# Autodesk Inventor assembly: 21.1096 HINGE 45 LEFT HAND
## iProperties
Created: 2007-01
Part Number: 21.1096 HINGE 45 LEFT HAND
Document SubType Name: Assembly
Designer: Andy Moles
Author: Andy Moles
